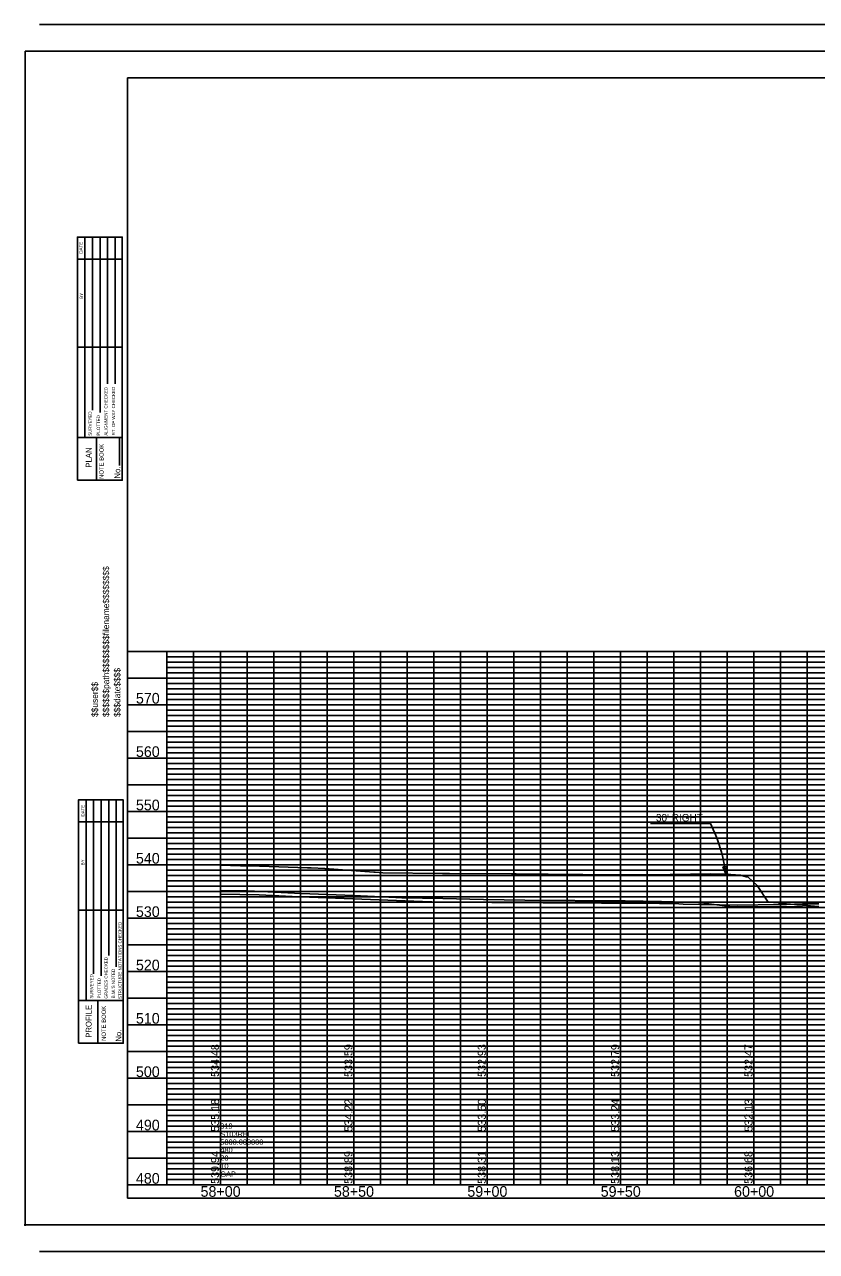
# Model space of a CAD drawing. Extents: x 178884 to 181858, y 178732 to 179192.
# Drawn here: x 178884.2 to 179181.1, y 178732.4 to 179192.4 of the extents above; entities that cross this region are included whole.
import ezdxf

# ---------------------------------------------------------------- set-up
doc = ezdxf.new("R2010")
doc.units = 0
for name, color, linetype in [('RD_DDB_ElevTX', 7, 'Continuous'), ('RD_DDB_Profile_EX', 7, 'Continuous'), ('RD_DDB_StaTX', 7, 'Continuous'), ('RD_DDB_StripGrade', 7, 'Continuous'), ('RD_GPK_Profile_Cell', 7, 'Continuous'), ('RD_SHT_Bndy', 7, 'Continuous'), ('RD_SHT_ID', 7, 'Continuous'), ('RD_SHT_IplotShp', 7, 'Continuous'), ('RD_SHT_MjGrid', 7, 'Continuous'), ('RD_SHT_MnGrid', 7, 'Continuous'), ('RD_SHT_SubGrid', 7, 'Continuous'), ('RD_SHT_TX', 7, 'Continuous'), ('RD_TX_Profile', 7, 'Continuous')]:
    doc.layers.add(name, color=color, linetype=linetype)

msp = doc.modelspace()

# ---------------------------------------------------------------- linework, layer by layer
at = {"layer": 'RD_DDB_Profile_EX'}
for points in [[(178957.57, 178877.27), (178965.09, 178877.02), (178972.2, 178876.81), (178990.21, 178876.22), (178991.67, 178876.18), (178996.73, 178876.01), (179015.17, 178874.58), (179015.63, 178874.55), (179018.51, 178874.32), (179040.85, 178874.15), (179043.5, 178874.13), (179066.68, 178873.95), (179068.48, 178873.94), (179092.53, 178873.76), (179093.46, 178873.75), (179118.7, 178873.58), (179141.39, 178873.92), (179143.61, 178873.91), (179147.02, 178873.96), (179148.97, 178873.75), (179152.63, 178873.48), (179154.75, 178872.85), (179155.47, 178872.68), (179158.85, 178869.57), (179162.99, 178863.41), (179166.79, 178863.05), (179169.81, 178862.76), (179172.83, 178862.48), (179173.64, 178862.4), (179175.86, 178862.22), (179178.88, 178861.97), (179181.9, 178861.71)], [(178957.57, 178867.75), (178967.87, 178867.58), (178987.84, 178866.61), (179007.49, 178865.83), (179023.34, 178865.06), (179025.67, 178864.95), (179040.93, 178864.68), (179056.29, 178864.41), (179071.76, 178864.14), (179109.35, 178863.86), (179122.94, 178863.62), (179136.88, 178863.18), (179148.54, 178861.67), (179163.63, 178861.66), (179166.79, 178861.63), (179169.81, 178861.6), (179172.83, 178861.57), (179175.86, 178861.54), (179178.88, 178861.51), (179180.16, 178861.5), (179181.9, 178861.78)], [(178957.57, 178866.34), (178972.16, 178866.1), (178984.48, 178865.5), (179033.36, 178863.56), (179035.24, 178863.46), (179036.82, 178863.44), (179038.41, 178863.41), (179040.01, 178863.38), (179078.54, 178863.1), (179122.27, 178862.91), (179127.89, 178862.87), (179131.13, 178862.63), (179151.5, 178862.24), (179166.79, 178862.47), (179169.81, 178862.52), (179172.83, 178862.6), (179175.86, 178862.67), (179178.56, 178862.74), (179178.88, 178862.74), (179181.9, 178862.7)]]:
    msp.add_lwpolyline(points, dxfattribs=at)
at = {"layer": 'RD_GPK_Profile_Cell'}
for q in [(178957.57, 178957.39), (181857.57, 178757.39), (178957.57, 178757.39)]:
    msp.add_line((178957.57, 178757.39), q, dxfattribs=at)
at = {"layer": 'RD_SHT_Bndy'}
for p, q in [((179593.83, 179192.39), (178889.83, 179192.39)), ((179593.83, 179182.39), (178889.83, 179182.39)), ((178903.99, 179071.43), (178903.99, 179112.71)), ((178906.83, 179037.55), (178906.83, 179112.71)), ((178909.65, 179047.79), (178909.65, 179112.71)), ((178912.49, 179046.89), (178912.49, 179112.71)), ((178915.31, 179057.65), (178915.31, 179112.71)), ((178918.15, 179057.65), (178918.15, 179112.71)), ((178903.99, 179104.45), (178920.79, 179104.45)), ((178903.99, 179071.43), (178920.79, 179071.43)), ((178903.99, 179037.51), (178920.79, 179037.51)), ((178911.19, 179021.51), (178911.19, 179037.51)), ((178919.79, 179027.13), (178919.79, 179037.49)), ((178903.99, 179021.51), (178920.79, 179021.51)), ((178922.77, 178957.39), (179592.77, 178957.39)), ((178937.57, 178957.39), (178937.57, 178757.39)), ((178904.39, 178901.67), (178904.39, 178860.39)), ((178907.23, 178901.67), (178907.23, 178826.49)), ((178910.05, 178901.67), (178910.05, 178836.51)), ((178912.89, 178901.67), (178912.89, 178835.71)), ((178915.71, 178901.67), (178915.71, 178843.35)), ((178918.55, 178901.67), (178918.55, 178839.13)), ((178904.39, 178893.41), (178921.19, 178893.41)), ((178904.39, 178860.39), (178921.19, 178860.39)), ((178904.39, 178826.47), (178921.19, 178826.47)), ((178904.39, 178810.47), (178904.39, 178826.47)), ((178911.59, 178810.47), (178911.59, 178826.47)), ((178904.39, 178810.47), (178921.19, 178810.47)), ((178922.77, 178757.39), (179592.77, 178757.39)), ((179593.83, 178742.39), (178889.83, 178742.39)), ((179593.83, 178732.39), (178889.83, 178732.39))]:
    msp.add_line(p, q, dxfattribs=at)
for points in [[(178922.77, 179172.39), (179592.77, 179172.39), (179592.77, 178752.39), (178922.77, 178752.39)], [(178903.99, 179021.51), (178903.99, 179112.71), (178920.79, 179112.71), (178920.79, 179021.51)], [(178904.39, 178810.47), (178904.39, 178901.67), (178921.19, 178901.67), (178921.19, 178810.47)]]:
    msp.add_lwpolyline(points, close=True, dxfattribs=at)
at = {"layer": 'RD_SHT_IplotShp'}
msp.add_lwpolyline([(178884.41, 179182.39), (179602.77, 179182.39), (179602.77, 178742.39), (178884.41, 178742.39)], close=True, dxfattribs=at)
msp.add_circle((178884.41, 178742.39), 0.243, dxfattribs=at)
at = {"layer": 'RD_SHT_MjGrid'}
for p, q in [((178957.57, 178957.39), (178957.57, 178757.39)), ((178977.57, 178957.39), (178977.57, 178757.39)), ((178997.57, 178957.39), (178997.57, 178757.39)), ((179017.57, 178957.39), (179017.57, 178757.39)), ((179037.57, 178957.39), (179037.57, 178757.39)), ((179057.57, 178957.39), (179057.57, 178757.39)), ((179077.57, 178957.39), (179077.57, 178757.39)), ((179097.57, 178957.39), (179097.57, 178757.39)), ((179117.57, 178957.39), (179117.57, 178757.39)), ((179137.57, 178957.39), (179137.57, 178757.39)), ((179157.57, 178957.39), (179157.57, 178757.39)), ((179177.57, 178957.39), (179177.57, 178757.39)), ((178922.77, 178937.39), (179592.77, 178937.39)), ((178922.77, 178917.39), (179592.77, 178917.39)), ((178922.77, 178897.39), (179592.77, 178897.39)), ((178922.77, 178877.39), (179592.77, 178877.39)), ((178922.77, 178857.39), (179592.77, 178857.39)), ((178922.77, 178837.39), (179592.77, 178837.39)), ((178922.77, 178817.39), (179592.77, 178817.39)), ((178922.77, 178797.39), (179592.77, 178797.39)), ((178922.77, 178777.39), (179592.77, 178777.39))]:
    msp.add_line(p, q, dxfattribs=at)
at = {"layer": 'RD_SHT_MnGrid'}
for p, q in [((178947.57, 178957.39), (178947.57, 178757.39)), ((178967.57, 178957.39), (178967.57, 178757.39)), ((178987.57, 178957.39), (178987.57, 178757.39)), ((179007.57, 178957.39), (179007.57, 178757.39)), ((179027.57, 178957.39), (179027.57, 178757.39)), ((179047.57, 178957.39), (179047.57, 178757.39)), ((179067.57, 178957.39), (179067.57, 178757.39)), ((179087.57, 178957.39), (179087.57, 178757.39)), ((179107.57, 178957.39), (179107.57, 178757.39)), ((179127.57, 178957.39), (179127.57, 178757.39)), ((179147.57, 178957.39), (179147.57, 178757.39)), ((179167.57, 178957.39), (179167.57, 178757.39)), ((178922.77, 178947.39), (179592.77, 178947.39)), ((178922.77, 178927.39), (179592.77, 178927.39)), ((178922.77, 178907.39), (179592.77, 178907.39)), ((178922.77, 178887.39), (179592.77, 178887.39)), ((178922.77, 178867.39), (179592.77, 178867.39)), ((178922.77, 178847.39), (179592.77, 178847.39)), ((178922.77, 178827.39), (179592.77, 178827.39)), ((178922.77, 178807.39), (179592.77, 178807.39)), ((178922.77, 178787.39), (179592.77, 178787.39)), ((178922.77, 178767.39), (179592.77, 178767.39))]:
    msp.add_line(p, q, dxfattribs=at)
at = {"layer": 'RD_SHT_SubGrid'}
for p, q in [((178937.59, 178955.39), (179577.49, 178955.39)), ((178937.59, 178953.39), (179577.27, 178953.39)), ((178937.59, 178951.39), (179577.49, 178951.39)), ((178937.61, 178949.39), (179577.49, 178949.39)), ((178937.59, 178945.39), (179577.49, 178945.39)), ((178937.59, 178943.39), (179577.07, 178943.39)), ((178937.59, 178941.39), (179577.27, 178941.39)), ((178937.59, 178939.39), (179577.49, 178939.39)), ((178937.59, 178935.39), (179577.49, 178935.39)), ((178937.59, 178933.39), (179577.49, 178933.39)), ((178937.59, 178931.39), (179577.27, 178931.39)), ((178937.59, 178929.39), (179577.49, 178929.39)), ((178937.59, 178925.39), (179577.07, 178925.39)), ((178937.59, 178923.39), (179577.07, 178923.39)), ((178937.59, 178921.39), (179577.27, 178921.39)), ((178937.59, 178919.39), (179577.27, 178919.39)), ((178937.59, 178915.39), (179577.07, 178915.39)), ((178937.59, 178913.39), (179577.27, 178913.39)), ((178937.59, 178911.39), (179577.07, 178911.39)), ((178937.61, 178909.39), (179577.49, 178909.39)), ((178937.59, 178905.39), (179577.27, 178905.39)), ((178937.59, 178903.39), (179577.27, 178903.39)), ((178937.59, 178901.39), (179577.27, 178901.39)), ((178937.59, 178899.39), (179577.27, 178899.39)), ((178937.63, 178895.39), (179577.07, 178895.39)), ((178937.61, 178891.39), (179577.27, 178891.39)), ((178937.63, 178893.39), (179577.07, 178893.39)), ((178937.59, 178885.39), (179577.27, 178885.39)), ((178937.61, 178889.39), (179577.27, 178889.39)), ((178937.59, 178883.39), (179577.27, 178883.39)), ((178937.59, 178881.39), (179577.07, 178881.39)), ((178937.59, 178879.39), (179577.27, 178879.39)), ((178937.59, 178879.39), (179577.27, 178879.39)), ((178937.59, 178875.39), (179577.49, 178875.39)), ((178937.59, 178873.39), (179577.49, 178873.39)), ((178937.59, 178871.39), (179577.49, 178871.39)), ((178937.59, 178869.39), (179577.49, 178869.39)), ((178937.59, 178865.39), (179577.49, 178865.39)), ((178937.59, 178863.39), (179577.49, 178863.39)), ((178937.59, 178861.39), (179577.49, 178861.39)), ((178937.59, 178859.39), (179577.49, 178859.39)), ((178937.59, 178855.39), (179577.51, 178855.39)), ((178937.59, 178853.39), (179577.51, 178853.39)), ((178937.59, 178851.39), (179577.51, 178851.39)), ((178937.59, 178849.39), (179577.51, 178849.39)), ((178937.59, 178845.39), (179577.51, 178845.39)), ((178937.59, 178843.39), (179577.51, 178843.39)), ((178937.59, 178841.39), (179577.51, 178841.39)), ((178937.59, 178839.39), (179577.51, 178839.39)), ((178937.59, 178835.39), (179577.51, 178835.39)), ((178937.59, 178833.39), (179577.51, 178833.39)), ((178937.59, 178831.39), (179577.51, 178831.39)), ((178937.59, 178829.39), (179577.51, 178829.39)), ((178937.59, 178825.39), (179577.51, 178825.39)), ((178937.61, 178825.39), (179577.51, 178825.39)), ((178937.59, 178823.39), (179577.51, 178823.39)), ((178937.61, 178821.39), (179577.41, 178821.39)), ((178937.61, 178819.39), (179577.41, 178819.39)), ((178937.59, 178813.39), (179577.55, 178813.39)), ((178937.59, 178811.39), (179577.55, 178811.39)), ((178937.61, 178815.39), (179577.49, 178815.39)), ((178937.61, 178809.39), (179577.55, 178809.39)), ((178937.59, 178805.39), (179577.55, 178805.39)), ((178937.59, 178803.39), (179577.55, 178803.39)), ((178937.59, 178801.39), (179577.55, 178801.39)), ((178937.61, 178799.39), (179577.55, 178799.39)), ((178937.59, 178795.39), (179577.55, 178795.39)), ((178937.59, 178793.39), (179577.55, 178793.39)), ((178937.59, 178791.39), (179577.55, 178791.39)), ((178937.59, 178789.39), (179577.51, 178789.39)), ((178937.61, 178785.39), (179577.41, 178785.39)), ((178937.59, 178783.39), (179577.51, 178783.39)), ((178937.59, 178781.39), (179577.51, 178781.39)), ((178937.59, 178779.39), (179577.51, 178779.39)), ((178937.63, 178775.39), (179577.51, 178775.39)), ((178937.59, 178773.39), (179577.51, 178773.39)), ((178937.59, 178771.39), (179577.51, 178771.39)), ((178937.59, 178769.39), (179577.51, 178769.39)), ((178937.63, 178765.39), (179577.51, 178765.39)), ((178937.63, 178763.39), (179577.51, 178763.39)), ((178937.63, 178761.39), (179577.51, 178761.39)), ((178937.63, 178759.39), (179577.51, 178759.39))]:
    msp.add_line(p, q, dxfattribs=at)
at = {"layer": 'RD_TX_Profile'}
msp.add_line((179141.28, 178892.83), (179118.88, 178892.83), dxfattribs=at)
msp.add_lwpolyline([(179145.98, 178876.55), (179147.02, 178873.96), (179147.42, 178876.73)], close=True, dxfattribs=at)
msp.add_arc((179091.06, 178867.23), 56.36, 6.8506, 27.0097, dxfattribs=at)

# ---------------------------------------------------------------- texts
at = {"layer": 'RD_DDB_ElevTX'}
for s, p in [('570', (178925.92, 178937.79)), ('560', (178925.92, 178917.79)), ('550', (178925.92, 178897.79)), ('540', (178925.92, 178877.79)), ('530', (178925.92, 178857.79)), ('520', (178925.92, 178837.79)), ('510', (178925.92, 178817.79)), ('500', (178925.92, 178797.79)), ('490', (178925.92, 178777.79)), ('480', (178925.92, 178757.79))]:
    msp.add_text(s, height=4, dxfattribs=at).set_placement(p)
at = {"layer": 'RD_DDB_StaTX'}
for s, p in [('58+00', (178950.16, 178752.89)), ('58+50', (179000.16, 178752.89)), ('59+00', (179050.16, 178752.89)), ('59+50', (179100.16, 178752.89)), ('60+00', (179150.16, 178752.89))]:
    msp.add_text(s, height=4, dxfattribs=at).set_placement(p)
at = {"layer": 'RD_DDB_StripGrade'}
for s, p in [('534.48', (178957.07, 178797.84)), ('533.59', (179007.07, 178797.84)), ('532.93', (179057.07, 178797.84)), ('532.79', (179107.07, 178797.84)), ('532.47', (179157.07, 178797.84)), ('535.18', (178957.1, 178777.31)), ('534.22', (179007.1, 178777.31)), ('533.50', (179057.1, 178777.31)), ('533.24', (179107.1, 178777.31)), ('532.13', (179157.1, 178777.31)), ('539.94', (178957.07, 178757.75)), ('538.89', (179007.07, 178757.75)), ('538.31', (179057.07, 178757.75)), ('538.13', (179107.07, 178757.75)), ('536.68', (179157.07, 178757.75))]:
    msp.add_text(s, height=3, rotation=90, dxfattribs=at).set_placement(p)
at = {"layer": 'RD_GPK_Profile_Cell'}
for s, p in [('919', (178957.57, 178778.39)), ('5800.000000', (178957.57, 178772.39)), ('S103REL', (178957.57, 178775.39)), ('480', (178957.57, 178769.39)), ('20', (178957.57, 178766.39)), ('10', (178957.57, 178763.39)), ('GAP', (178957.57, 178760.39))]:
    msp.add_text(s, height=2, dxfattribs=at).set_placement(p)
at = {"layer": 'RD_SHT_ID'}
for s, p in [('$$$$$$path$$$$$$$$filename$$$$$$$$', (178915.88, 178932.79)), ('$$$date$$$$', (178920.09, 178932.79)), ('$$user$$', (178911.67, 178932.79))]:
    msp.add_text(s, height=2.352, rotation=90, dxfattribs=at).set_placement(p)
at = {"layer": 'RD_SHT_TX'}
for s, height, p in [('DATE', 1.2, (178905.93, 179106.49)), ('BY', 1.2, (178906.07, 179089.59)), ('ALIGNMENT CHECKED', 1.2, (178915.29, 179038.29)), ('RT. OF WAY CHECKED', 1.2, (178918.13, 179038.35)), ('SURVEYED', 1.2, (178909.33, 179038.21)), ('PLOTTED', 1.2, (178912.45, 179038.29)), ('PLAN', 2.16, (178909.29, 179026.27)), ('NOTE BOOK', 1.6, (178913.81, 179022.06)), ('No.', 2.16, (178920.05, 179022.19)), ('DATE', 1.2, (178906.63, 178895.45)), ('BY', 1.2, (178906.63, 178877.17)), ('STRUCTURE NOTATIONS CHECKED', 1.2, (178920.55, 178827.07)), ('GRADES CHECKED', 1.2, (178915.33, 178827.21)), ('SURVEYED', 1.2, (178909.91, 178827.21)), ('PLOTTED', 1.2, (178912.75, 178827.25)), ("B.M.'S NOTED", 1.2, (178918.03, 178827.31)), ('PROFILE', 2.16, (178909.29, 178812.51)), ('NOTE BOOK', 1.6, (178914.67, 178811.36)), ('No.', 2.16, (178920.45, 178811.05))]:
    msp.add_text(s, height=height, rotation=90, dxfattribs=at).set_placement(p)
at = {"layer": 'RD_TX_Profile'}
msp.add_text("30' RIGHT", height=2.8, dxfattribs=at).set_placement((179120.88, 178893.63))

doc.saveas('drawing.dxf')
